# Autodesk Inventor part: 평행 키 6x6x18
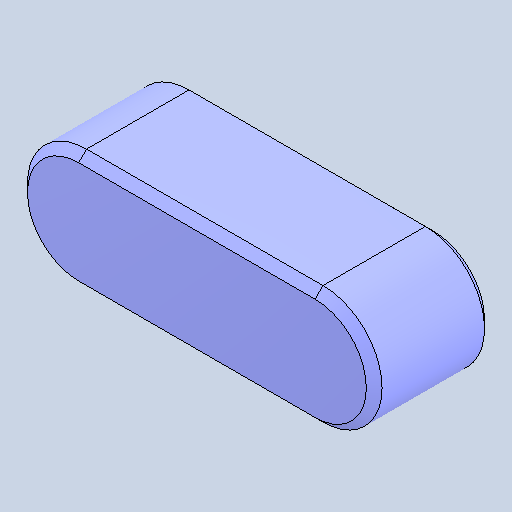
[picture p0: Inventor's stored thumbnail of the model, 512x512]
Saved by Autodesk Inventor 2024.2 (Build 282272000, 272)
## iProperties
Created: 2026-01
Part Number: 평행 키 6x6x18
Material: 강철, 연강
Description: 키 및 해당 키홈
Document SubType Name: Modeling
Designer: home
Density: 7.85 g/cm^3
Appearance: 기본값
Author: jhkim
Sending System: Autodesk Inventor 2026
Preprocessor: ST-DEVELOPER v20.1
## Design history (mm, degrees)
feature "Solid1"
node "솔리드1"
